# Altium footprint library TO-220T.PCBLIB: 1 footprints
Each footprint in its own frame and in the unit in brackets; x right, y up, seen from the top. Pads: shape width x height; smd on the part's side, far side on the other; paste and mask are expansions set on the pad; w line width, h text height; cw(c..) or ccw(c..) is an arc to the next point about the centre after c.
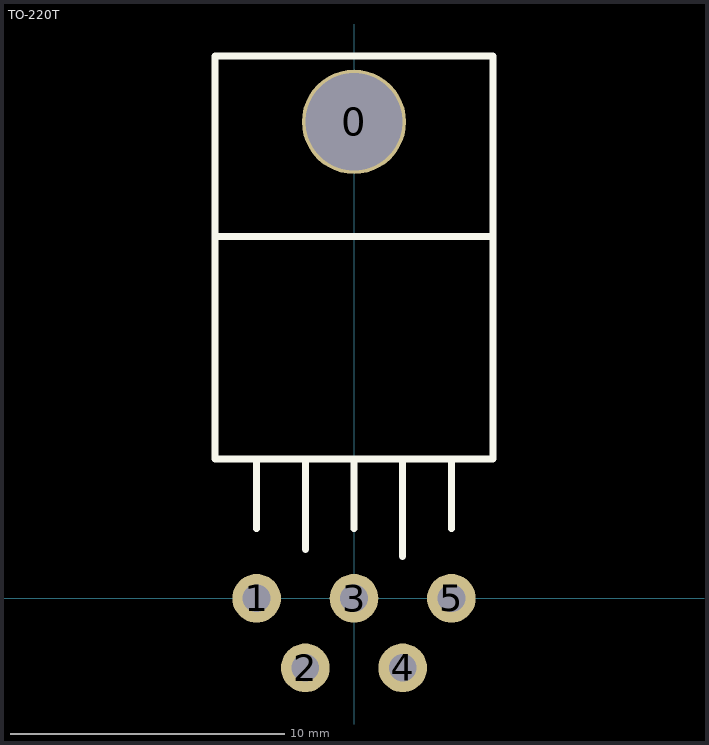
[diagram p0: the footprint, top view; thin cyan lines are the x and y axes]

## TO-220T [mil]
pads (6):
  round 150 hole 140: 0(0,685)
  round 70 hole 40: 1(-140,0) 2(-70,-100) 3(0,0) 4(70,-100) 5(140,0)
Top Overlay:
  lines w10: -140,100 -140,200 ; -70,70 -70,200 ; 0,100 0,200 ; 70,60 70,195 ; 115,200 120,200 ; 140,100 140,200 ; -200,520 -200,780 200,780 200,520 ; -200,520 200,520 ; -200,520 -200,200 200,200 200,520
